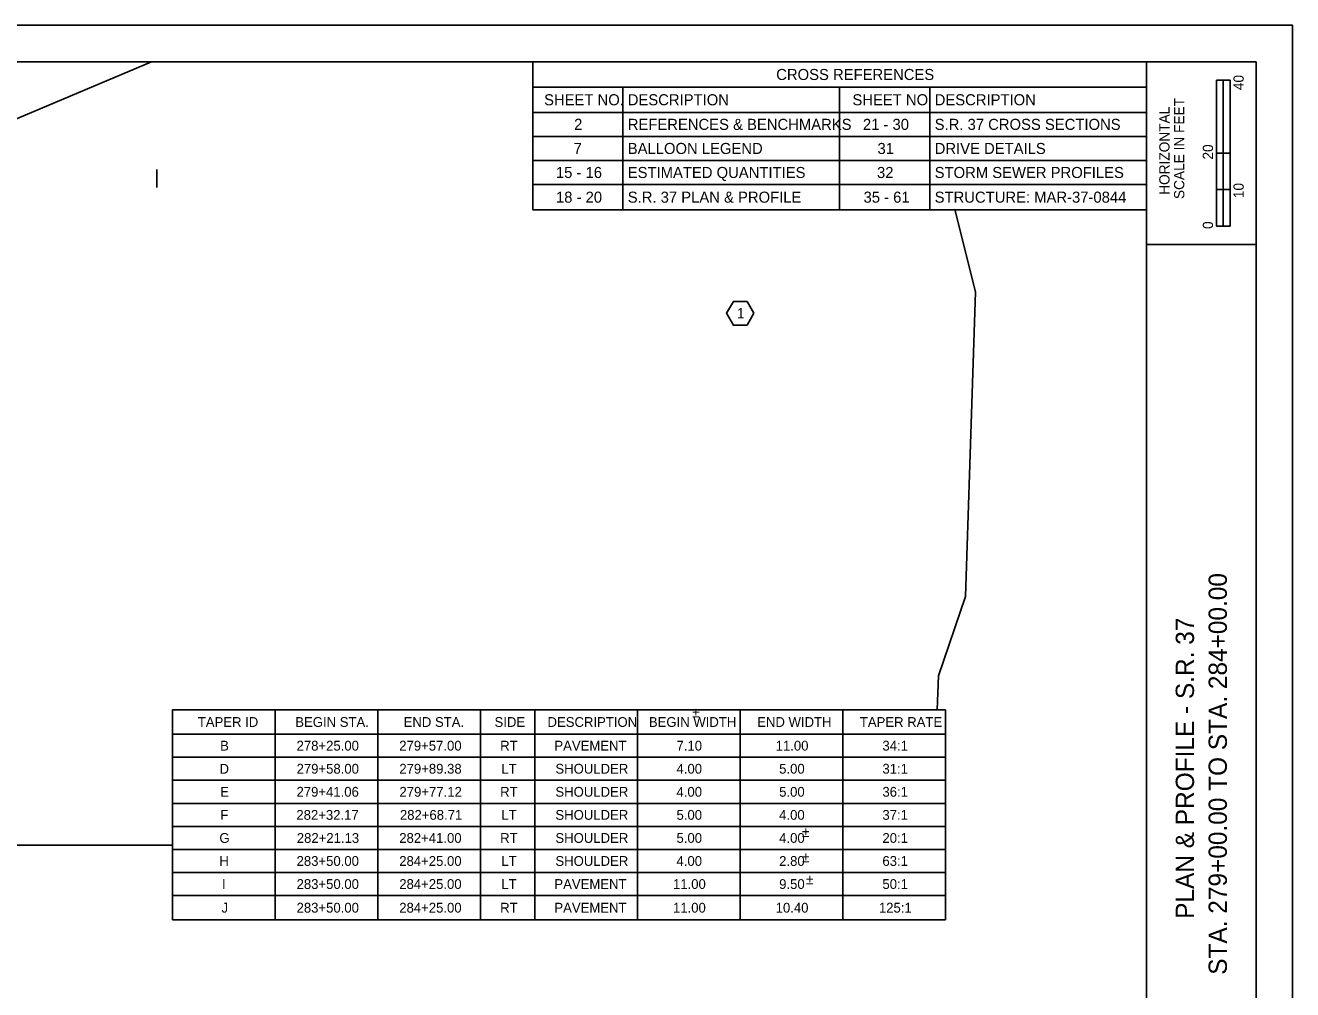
# Model space of a CAD drawing. Extents: x -0.7 to 34, y 0 to 22.
# Drawn here: x 16.66 to 34, y 8.79 to 22 of the extents above; entities that cross this region are included whole.
import ezdxf

# ---------------------------------------------------------------- set-up
doc = ezdxf.new("R2010")
doc.units = 0
for name, color, linetype in [('DT_X_Contour_Text', 7, 'Continuous'), ('PV_X_Shoulder_Aggregate', 7, 'Continuous'), ('SH_Border', 7, 'Continuous'), ('SH_Data', 7, 'Continuous'), ('SH_Masking', 7, 'Continuous'), ('SH_Text', 7, 'Continuous')]:
    doc.layers.add(name, color=color, linetype=linetype)

msp = doc.modelspace()

# ---------------------------------------------------------------- linework, layer by layer
at = {"layer": 'DT_X_Contour_Text'}
msp.add_line((18.455, 19.779), (18.455, 20.027), dxfattribs=at)
at = {"layer": 'PV_X_Shoulder_Aggregate'}
msp.add_lwpolyline([(4.106, 19.88), (4.213, 20.484), (7.57, 20.72), (7.57, 19.635), (9.729, 19.709), (11.352, 19.738), (13.596, 19.679), (15.042, 20.09), (18.384, 21.5), (21.48, 21.5), (23.6, 21.5), (23.6, 19.474), (29.375, 19.479), (29.66, 18.349), (29.525, 14.178), (29.153, 13.093), (29.136, 12.624), (18.669, 12.624), (18.669, 10.771), (4.424, 10.771), (4.355, 12.752), (3.755, 13.672), (3.53, 17.93), (4.145, 18.748)], close=True, dxfattribs=at)
at = {"layer": 'SH_Border'}
for p, q in [((32, 0.5), (32, 21.5)), ((32, 19), (33.5, 19))]:
    msp.add_line(p, q, dxfattribs=at)
msp.add_lwpolyline([(1.5, 21.5), (33.5, 21.5), (33.5, 0.5), (1.5, 0.5)], close=True, dxfattribs=at)
at = {"layer": 'SH_Data'}
msp.add_lwpolyline([(0, 0), (34, 0), (34, 22), (0, 22)], close=True, dxfattribs=at)
at = {"layer": 'SH_Masking'}
for p, q in [((23.6, 21.5), (32, 21.5)), ((23.6, 21.5), (23.6, 19.474)), ((32, 21.5), (32, 19.474)), ((23.6, 21.154), (32, 21.154)), ((24.835, 21.154), (24.835, 19.474)), ((27.8, 21.154), (27.8, 19.474)), ((29.035, 21.154), (29.035, 19.474)), ((23.6, 20.808), (32, 20.808)), ((23.6, 20.479), (32, 20.479)), ((23.6, 20.149), (32, 20.149)), ((23.6, 19.82), (32, 19.82)), ((23.6, 19.474), (32, 19.474))]:
    msp.add_line(p, q, dxfattribs=at)
msp.add_lwpolyline([(26.627, 18.057), (26.533, 18.22), (26.346, 18.22), (26.252, 18.057), (26.346, 17.895), (26.533, 17.895)], close=True, dxfattribs=at)
at = {"layer": 'SH_Text'}
for p, q in [((23.6, 21.5), (32, 21.5)), ((32, 21.5), (32, 19.474)), ((32.957, 19.25), (32.957, 21.25)), ((33.144, 21.25), (32.957, 21.25)), ((32.957, 20.25), (32.957, 21.25)), ((32.957, 21.25), (33.05, 21.25)), ((33.05, 21.25), (33.051, 21.25)), ((33.051, 21.25), (33.051, 20.25)), ((33.144, 21.25), (33.144, 19.25)), ((33.051, 20.25), (32.957, 20.25)), ((33.143, 20.25), (33.05, 20.25)), ((33.05, 20.25), (33.05, 19.75)), ((33.143, 19.75), (33.143, 20.25)), ((33.05, 19.75), (32.957, 19.75)), ((32.957, 19.75), (32.957, 19.25)), ((33.05, 19.25), (33.05, 19.75)), ((33.05, 19.75), (33.143, 19.75)), ((33.144, 19.25), (32.957, 19.25)), ((32.957, 19.25), (33.05, 19.25)), ((18.669, 12.624), (29.25, 12.624)), ((18.669, 12.624), (18.669, 9.75)), ((20.075, 12.624), (20.075, 9.75)), ((21.48, 12.624), (21.48, 9.75)), ((22.886, 12.624), (22.886, 9.75)), ((23.628, 12.624), (23.628, 9.75)), ((25.034, 12.624), (25.034, 9.75)), ((26.439, 12.624), (26.439, 9.75)), ((27.845, 12.624), (27.845, 9.75)), ((29.25, 12.624), (29.25, 9.75)), ((18.669, 12.293), (29.25, 12.293)), ((18.669, 11.977), (29.25, 11.977)), ((18.669, 11.661), (29.25, 11.661)), ((18.669, 11.345), (29.25, 11.345)), ((18.669, 11.029), (29.25, 11.029)), ((18.669, 10.714), (29.25, 10.714)), ((18.669, 10.398), (29.25, 10.398)), ((18.669, 10.082), (29.25, 10.082)), ((18.669, 9.75), (29.25, 9.75))]:
    msp.add_line(p, q, dxfattribs=at)

# ---------------------------------------------------------------- texts
at = {"layer": 'SH_Masking'}
for s, height, p in [('CROSS REFERENCES', 0.15153, (26.933, 21.251)), ('SHEET NO.', 0.1515, (23.756, 20.905)), ('DESCRIPTION', 0.15153, (24.901, 20.905)), ('SHEET NO', 0.1515, (27.976, 20.905)), ('DESCRIPTION', 0.15153, (29.101, 20.905)), ('2', 0.152, (24.167, 20.568)), ('REFERENCES & BENCHMARKS', 0.15153, (24.901, 20.568)), ('21 - 30', 0.1515, (28.119, 20.568)), ('S.R. 37 CROSS SECTIONS', 0.15153, (29.101, 20.568)), ('7', 0.152, (24.16, 20.238)), ('BALLOON LEGEND', 0.15153, (24.901, 20.238)), ('31', 0.1515, (28.319, 20.238)), ('DRIVE DETAILS', 0.15153, (29.101, 20.238)), ('15 - 16', 0.1515, (23.918, 19.909)), ('ESTIMATED QUANTITIES', 0.15153, (24.901, 19.909)), ('32', 0.1515, (28.312, 19.909)), ('STORM SEWER PROFILES', 0.15153, (29.101, 19.909)), ('18 - 20', 0.1515, (23.919, 19.571)), ('S.R. 37 PLAN & PROFILE', 0.15153, (24.901, 19.571)), ('35 - 61', 0.1515, (28.128, 19.571)), ('STRUCTURE: MAR-37-0844', 0.15153, (29.101, 19.571)), ('TAPER ID', 0.1342, (19.017, 12.392)), ('BEGIN STA.', 0.1342, (20.351, 12.392)), ('END STA.', 0.1342, (21.834, 12.392)), ('SIDE', 0.1342, (23.078, 12.392)), ('DESCRIPTION', 0.13423, (23.803, 12.392)), ('BEGIN WIDTH', 0.13423, (25.19, 12.392)), ('±', 0.14, (25.782, 12.521)), ('END WIDTH', 0.1342, (26.673, 12.392)), ('TAPER RATE', 0.1342, (28.077, 12.392)), ('B', 0.134, (19.323, 12.068)), ('278+25.00', 0.1342, (20.369, 12.068)), ('279+57.00', 0.1342, (21.774, 12.068)), ('RT', 0.1342, (23.155, 12.068)), ('PAVEMENT', 0.1342, (23.897, 12.068)), ('7.10', 0.1342, (25.568, 12.068)), ('11.00', 0.1342, (26.925, 12.068)), ('34:1', 0.1342, (28.386, 12.068)), ('D', 0.134, (19.315, 11.752)), ('279+58.00', 0.1342, (20.369, 11.752)), ('279+89.38', 0.1342, (21.775, 11.752)), ('LT', 0.1342, (23.171, 11.752)), ('SHOULDER', 0.1342, (23.911, 11.752)), ('4.00', 0.1342, (25.568, 11.752)), ('5.00', 0.1342, (26.973, 11.752)), ('31:1', 0.1342, (28.386, 11.752)), ('E', 0.134, (19.324, 11.436)), ('279+41.06', 0.1342, (20.368, 11.436)), ('279+77.12', 0.1342, (21.777, 11.436)), ('RT', 0.1342, (23.155, 11.436)), ('SHOULDER', 0.1342, (23.911, 11.436)), ('4.00', 0.1342, (25.568, 11.436)), ('5.00', 0.1342, (26.973, 11.436)), ('36:1', 0.1342, (28.386, 11.436)), ('F', 0.134, (19.325, 11.12)), ('282+32.17', 0.1342, (20.366, 11.12)), ('282+68.71', 0.1342, (21.783, 11.12)), ('LT', 0.1342, (23.171, 11.12)), ('SHOULDER', 0.1342, (23.911, 11.12)), ('5.00', 0.1342, (25.568, 11.12)), ('4.00', 0.1342, (26.973, 11.12)), ('37:1', 0.1342, (28.386, 11.12)), ('G', 0.134, (19.313, 10.804)), ('282+21.13', 0.1342, (20.372, 10.804)), ('282+41.00', 0.1342, (21.774, 10.804)), ('RT', 0.1342, (23.155, 10.804)), ('SHOULDER', 0.1342, (23.911, 10.804)), ('5.00', 0.1342, (25.568, 10.804)), ('4.00', 0.1342, (26.973, 10.804)), ('±', 0.14, (27.286, 10.883)), ('20:1', 0.1342, (28.386, 10.804)), ('H', 0.134, (19.313, 10.489)), ('283+50.00', 0.1342, (20.369, 10.489)), ('284+25.00', 0.1342, (21.774, 10.489)), ('LT', 0.1342, (23.171, 10.489)), ('SHOULDER', 0.1342, (23.911, 10.489)), ('4.00', 0.1342, (25.568, 10.489)), ('2.80', 0.1342, (26.973, 10.489)), ('±', 0.14, (27.286, 10.538)), ('63:1', 0.1342, (28.386, 10.489)), ('I', 0.134, (19.349, 10.173)), ('283+50.00', 0.1342, (20.369, 10.173)), ('284+25.00', 0.1342, (21.774, 10.173)), ('LT', 0.1342, (23.171, 10.173)), ('PAVEMENT', 0.1342, (23.897, 10.173)), ('11.00', 0.1342, (25.52, 10.173)), ('9.50', 0.1342, (26.973, 10.173)), ('±', 0.14, (27.34, 10.234)), ('50:1', 0.1342, (28.386, 10.173)), ('J', 0.134, (19.342, 9.849)), ('283+50.00', 0.1342, (20.369, 9.849)), ('284+25.00', 0.1342, (21.774, 9.849)), ('RT', 0.1342, (23.155, 9.849)), ('PAVEMENT', 0.1342, (23.897, 9.849)), ('11.00', 0.1342, (25.52, 9.849)), ('10.40', 0.1342, (26.925, 9.849)), ('125:1', 0.1342, (28.338, 9.849))]:
    msp.add_text(s, height=height, dxfattribs=at).set_placement(p)
msp.add_text('1', height=0.14, rotation=360, dxfattribs=at).set_placement((26.394, 17.987))
at = {"layer": 'SH_Text'}
for s, height, p in [('40', 0.14, (33.33, 21.112)), ('SCALE IN FEET', 0.14, (32.517, 19.621)), ('HORIZONTAL', 0.14, (32.315, 19.679)), ('20', 0.14, (32.91, 20.162)), ('10', 0.14, (33.33, 19.633)), ('0', 0.14, (32.91, 19.211)), ('STA. 279+00.00 TO STA. 284+00.00', 0.25, (33.1, 8.998)), ('PLAN & PROFILE - S.R. 37', 0.25, (32.65, 9.764))]:
    msp.add_text(s, height=height, rotation=90, dxfattribs=at).set_placement(p)

doc.saveas('drawing.dxf')
